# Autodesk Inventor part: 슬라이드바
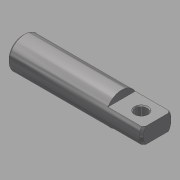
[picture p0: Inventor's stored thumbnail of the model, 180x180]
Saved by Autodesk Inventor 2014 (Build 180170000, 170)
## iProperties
Created: 2015-12
Part Number: 슬라이드바
Material: 스테인리스강
Document SubType Name: Modeling
Designer: mduedu
Density: 8.08 g/cm^3
Appearance: 반광택
Author: mduedu
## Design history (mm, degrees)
sketch "스케치1"
  geometry: L1 (-34, 0)-(34, 0); L2 (-34, 0)-(-34, 8); L3 (-34, 8)-(34, 8); L4 (34, 8)-(34, 0); 2 further points
  constraints: 8 end point, 2 perpendicular, 1 coincident, 1 horizontal, 1 midpoint, 1 vertical
  dimensions: "d0" = 68 distance of L2.end L3.end; "d2" = 16 diameter of L3 L1
revolve "회전1" sketch "스케치1" stored, may be unused: angle "d3" = 90 deg
sketch "스케치2"
  geometry: L1 (34, -8)-(34, 8) reference; L2 (0, 0)-(34, 0); L3 (34, 4)-(16, 4); L4 (16, 4)-(16, 8); L5 (16, 8)-(34, 8); L6 (34, 8)-(34, 4); L7 (-34, 8)-(34, 8) reference
  constraints: 10 end point, 2 parallel, 1 collinear, 1 horizontal, 1 midpoint, 1 perpendicular, 1 point on line
  dimensions: "d4" = 18 distance of L4.end L5.end; "d6" = 4 distance between parallel lines of L3 L2
extrude "돌출1" cut sketch "스케치2" stored distance "d8" = 10; taper "d9" = 0 deg
sketch "스케치3"
  geometry: L1 (0, 0)-(0, -13.856) reference; 2 further points
  constraints: 1 horizontal alignment
  dimensions: "d10" = 10 distance from line of point (10, -6.928) L1
hole "구멍1" sketch "스케치3" at (10, -6.928) diameter "d11" = 6; stored, may be unused: countersink angle "d15" = 90 deg, drill point angle "d17" = 118 deg; dims "d12" = 6, "d13" = 4, "d14" = 2, "d16" = 8
chamfer "모따기1" distance "d18" = 0.5; stored, may be unused: second distance "d19" = 2, angle "d20" = 45 deg
chamfer "모따기2" distance "d21" = 1; stored, may be unused: second distance "d22" = 2, angle "d23" = 45 deg
hole "구멍2" diameter "d26" = 4.917; stored, may be unused: countersink angle "d30" = 90 deg, drill point angle "d32" = 118 deg; dims "d24" = 10, "d25" = 10, "d27" = 12, "d28" = 4, "d29" = 2, "d31" = 13
chamfer "모따기3" distance "d33" = 1; stored, may be unused: second distance "d34" = 2, angle "d35" = 45 deg
node "솔리드1"
mirror "대칭1"
